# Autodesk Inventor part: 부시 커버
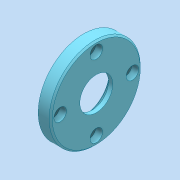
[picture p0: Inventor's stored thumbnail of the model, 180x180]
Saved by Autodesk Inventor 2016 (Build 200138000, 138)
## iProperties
Created: 2024-08
Part Number: 부시 커버
Material: 일반
Document SubType Name: Modeling
Designer: pc-7
Density: 1 g/cm^3
Appearance: 기본값
Author: jhkim
Sending System: Autodesk Inventor 2025
Preprocessor: ST-DEVELOPER v20
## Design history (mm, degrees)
node "부시 커버1"
node "솔리드2"
node "솔리드1"
